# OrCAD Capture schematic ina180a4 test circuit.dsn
size A
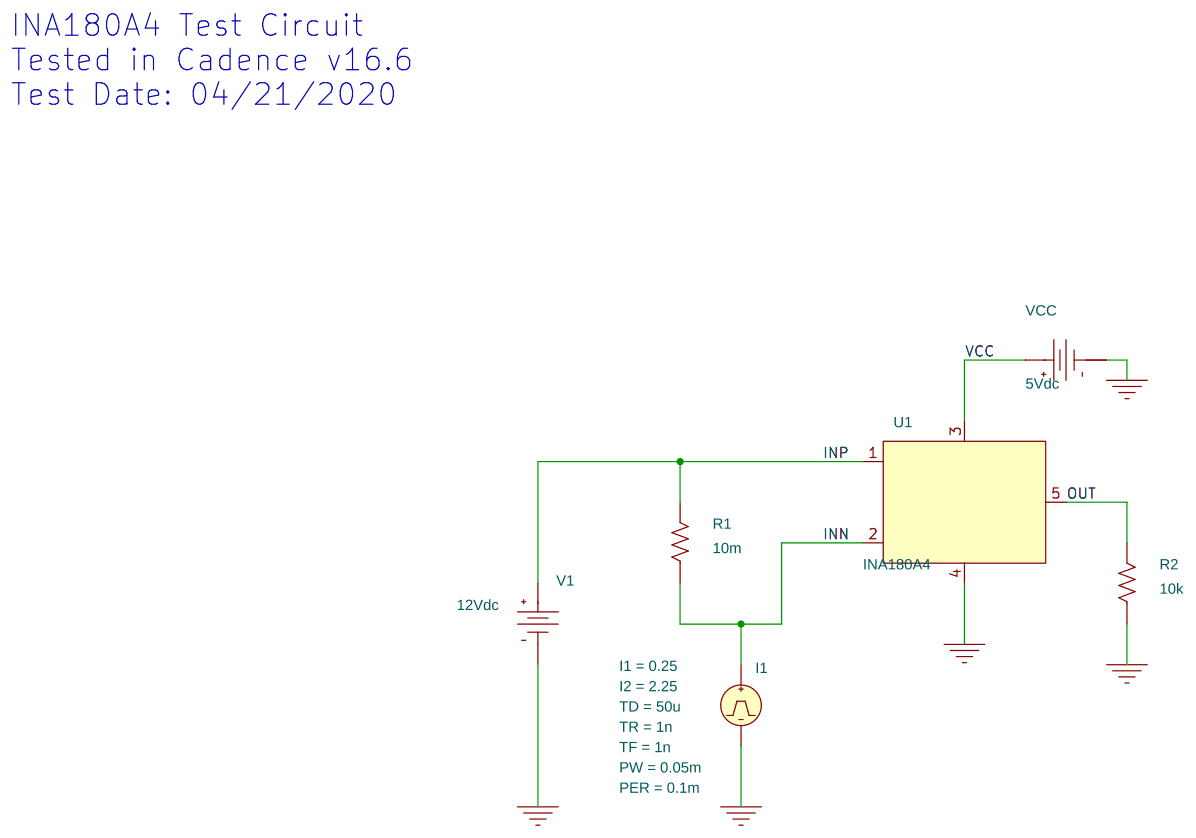
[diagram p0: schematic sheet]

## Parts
I1  IPULSE
R1  10m  [AX/RC05]
R2  10k  [AX/RC05]
U1  INA180A4
V1  VDC
VCC  VDC

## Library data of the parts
I1 = IPULSE: I1: 0.25; I2: 2.25; PER: 0.1m; PW: 0.05m; TD: 50u; TF: 1n; TR: 1n
R1 R2 = R
U1 = INA180A4
V1 = VDC: DC: 12Vdc
VCC = VDC: DC: 5Vdc

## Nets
VCC: U1.3(VCC) VCC.0(+)
0: I1.2(-) R2.1 U1.4(GND) V1.1(-) VCC.1(-)
INN: I1.1(+) R1.1 U1.2(INN)
INP: R1.2 U1.1(INP) V1.0(+)
OUT: R2.2 U1.5(OUT)

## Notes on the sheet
- INA180A4 Test Circuit
  Tested in Cadence v16.6
  Test Date: 04/21/2020
